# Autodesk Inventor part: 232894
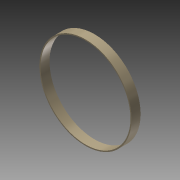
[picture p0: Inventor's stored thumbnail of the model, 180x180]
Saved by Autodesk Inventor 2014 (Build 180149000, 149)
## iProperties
Shininess: 20.0
Length Units: 11272
Angle Units: 11279
Time Units: 11290
Mass Units: 11286
Length Display Precision: 3
Angle Display Precision: 2
Company: Autodesk, Inc.
Created: 2002-06
Part Number: 232894
Material: Generic
Description: FILTER, STRAINER
Document SubType Name: Modeling
Designer: Autodesk, Inc.
Density: 1 g/cm^3
Mass: 8.14453 g
Surface Area: 115.434 cm^2
Volume: 8.14453 cm^3
Appearance: Wheat
Density: 0.0
Volumn: 0.0
Area: 0.0
PropertySet Name: Model Information
Control State: 0
Master: False
Checked Out: False
Last Check In By: JT
Last Check In Date: 2003-06-20
Title: FILTER, STRAINER
Author: Autodesk, Inc.
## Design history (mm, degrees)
sketch "Sketch1"
  geometry: C1 r 63.5 at (0, 0); C2 r 65.088 at (0, 0); 1 further point
  constraints: 2 centre point, 2 coincident
  dimensions: "d3" = 127 diameter of C1; "d4" = 1.5875 radial gap between concentric circles of C2 C1
extrude "Extrusion2" new body sketch "Sketch1" distance "d5" = 12.7; taper "d6" = 0 deg
body "Solid1"
